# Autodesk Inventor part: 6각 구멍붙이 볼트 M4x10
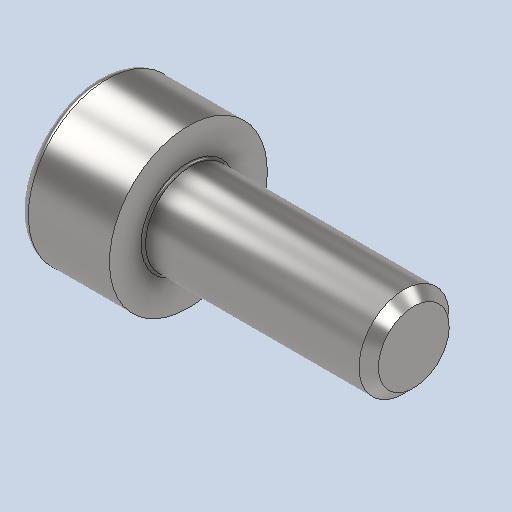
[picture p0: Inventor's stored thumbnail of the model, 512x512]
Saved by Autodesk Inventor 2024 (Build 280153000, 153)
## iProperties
Created: 2025-10
Part Number: 6각 구멍붙이 볼트 M4x10
Material: 강철, 연강
Description: 6각머리 태핑 나사
Document SubType Name: Modeling
Designer: EDU03
Density: 7.85 g/cm^3
Appearance: 기본값
Author: jhkim
Sending System: Autodesk Inventor 2026
Preprocessor: ST-DEVELOPER v20.1
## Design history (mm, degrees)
feature "Solid1"
node "솔리드1"
